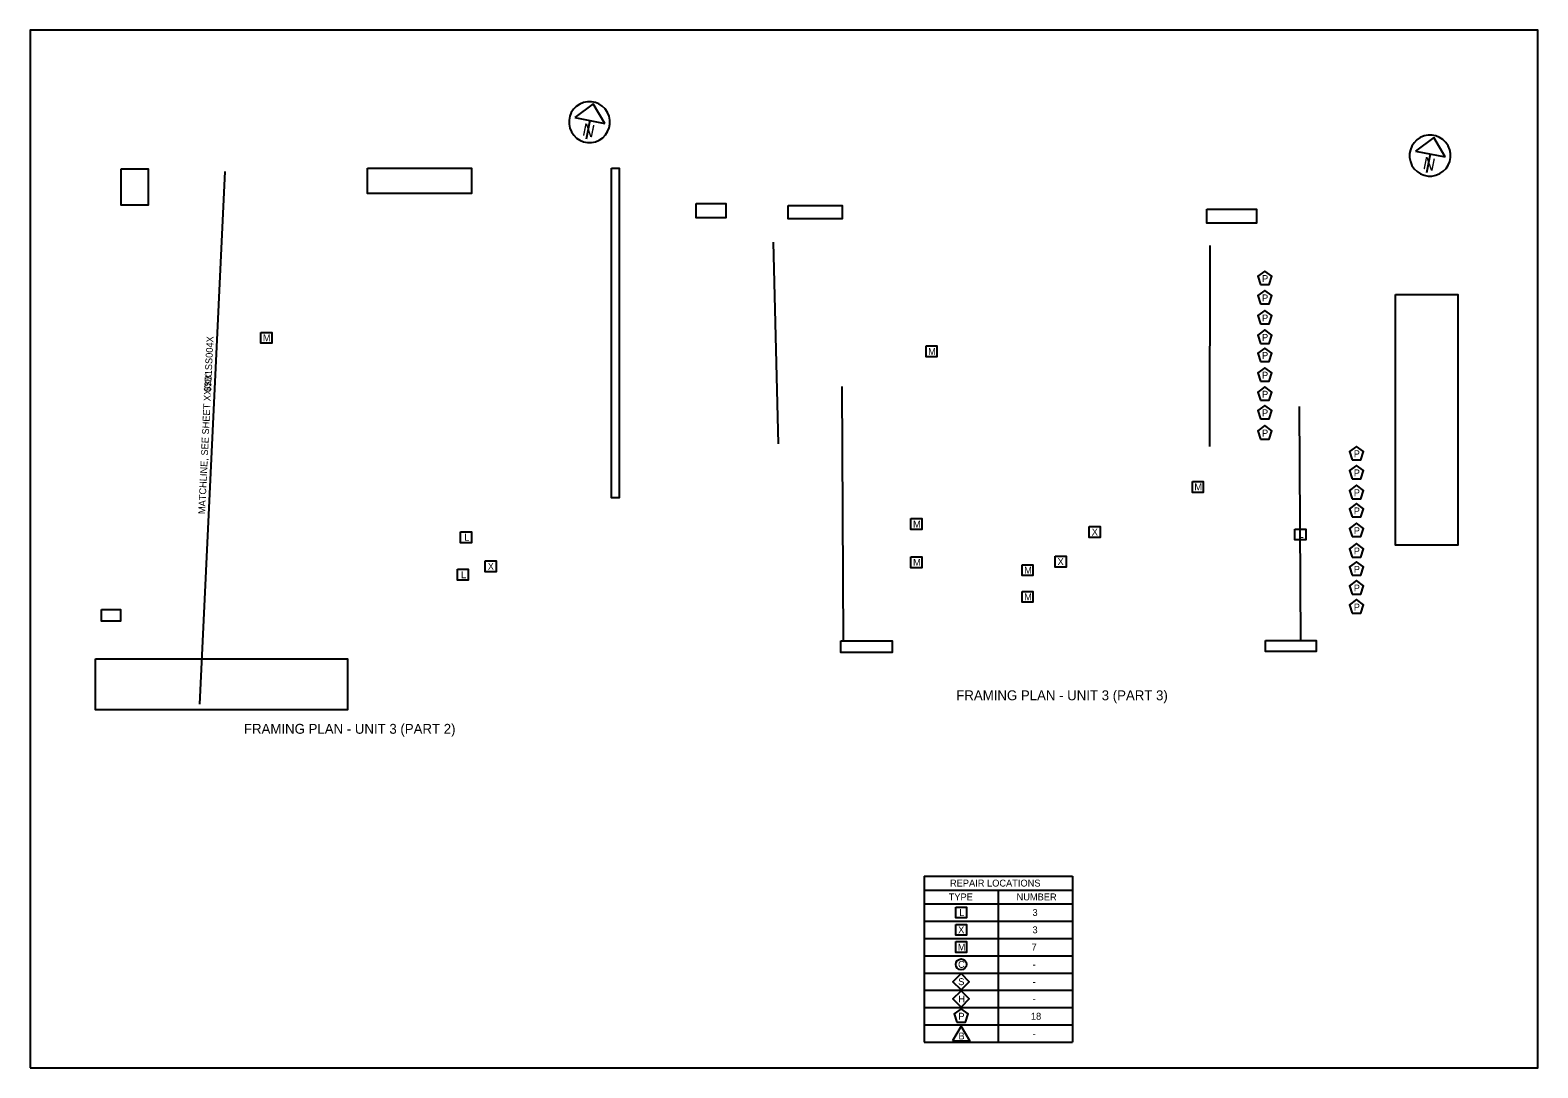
# Model space of a CAD drawing. Extents: x 100 to 130.5, y 100 to 121.
import ezdxf

# ---------------------------------------------------------------- set-up
doc = ezdxf.new("R2010")
doc.units = 0
for name, color, linetype in [('BR_P_Gen_Text', 7, 'Continuous'), ('BR_X_Sub_Centerline', 7, 'Continuous'), ('BR_X_Sub_Text', 7, 'Continuous'), ('SC_Scratch1', 7, 'Continuous'), ('SH_Data', 7, 'Continuous'), ('SH_Masking', 7, 'Continuous')]:
    doc.layers.add(name, color=color, linetype=linetype)

msp = doc.modelspace()

# ---------------------------------------------------------------- linework, layer by layer
at = {"layer": 'BR_P_Gen_Text'}
for p, q in [((103.94, 118.139), (103.427, 107.361)), ((118.083, 103.879), (118.083, 100.519)), ((118.083, 103.879), (121.083, 103.879)), ((121.083, 103.879), (121.083, 100.519)), ((118.083, 103.599), (121.083, 103.599)), ((119.583, 103.599), (119.583, 100.519)), ((118.083, 103.319), (121.083, 103.319)), ((118.083, 102.969), (121.083, 102.969)), ((118.083, 102.619), (121.083, 102.619)), ((118.083, 102.269), (121.083, 102.269)), ((118.083, 101.919), (121.083, 101.919)), ((118.083, 101.569), (121.083, 101.569)), ((118.083, 101.219), (121.083, 101.219)), ((118.083, 100.869), (121.083, 100.869)), ((118.083, 100.519), (121.083, 100.519))]:
    msp.add_line(p, q, dxfattribs=at)
for points in [[(124.888, 115.85), (125.064, 115.85), (125.119, 116.018), (124.976, 116.122), (124.833, 116.018)], [(124.888, 115.459), (125.064, 115.459), (125.119, 115.627), (124.976, 115.731), (124.833, 115.627)], [(124.888, 115.054), (125.064, 115.054), (125.119, 115.222), (124.976, 115.325), (124.833, 115.222)], [(104.666, 114.883), (104.886, 114.883), (104.886, 114.663), (104.666, 114.663)], [(124.888, 114.66), (125.064, 114.66), (125.119, 114.828), (124.976, 114.932), (124.833, 114.828)], [(118.124, 114.609), (118.344, 114.609), (118.344, 114.389), (118.124, 114.389)], [(124.888, 114.296), (125.064, 114.296), (125.119, 114.463), (124.976, 114.567), (124.833, 114.463)], [(124.888, 113.896), (125.064, 113.896), (125.119, 114.064), (124.976, 114.167), (124.833, 114.064)], [(124.888, 113.51), (125.064, 113.51), (125.119, 113.677), (124.976, 113.781), (124.833, 113.677)], [(124.888, 113.133), (125.064, 113.133), (125.119, 113.301), (124.976, 113.405), (124.833, 113.301)], [(124.888, 112.725), (125.064, 112.725), (125.119, 112.892), (124.976, 112.996), (124.833, 112.892)], [(126.744, 112.306), (126.92, 112.306), (126.975, 112.474), (126.832, 112.577), (126.689, 112.474)], [(126.744, 111.919), (126.92, 111.919), (126.975, 112.086), (126.832, 112.19), (126.689, 112.086)], [(123.511, 111.866), (123.731, 111.866), (123.731, 111.646), (123.511, 111.646)], [(126.744, 111.517), (126.92, 111.517), (126.975, 111.685), (126.832, 111.789), (126.689, 111.685)], [(126.744, 111.149), (126.92, 111.149), (126.975, 111.316), (126.832, 111.42), (126.689, 111.316)], [(117.819, 111.114), (118.039, 111.114), (118.039, 110.894), (117.819, 110.894)], [(126.744, 110.75), (126.92, 110.75), (126.975, 110.917), (126.832, 111.021), (126.689, 110.917)], [(108.709, 110.847), (108.929, 110.847), (108.929, 110.627), (108.709, 110.627)], [(121.425, 110.953), (121.645, 110.953), (121.645, 110.733), (121.425, 110.733)], [(125.584, 110.904), (125.804, 110.904), (125.804, 110.684), (125.584, 110.684)], [(126.744, 110.338), (126.92, 110.338), (126.975, 110.506), (126.832, 110.61), (126.689, 110.506)], [(109.208, 110.259), (109.428, 110.259), (109.428, 110.039), (109.208, 110.039)], [(117.819, 110.341), (118.039, 110.341), (118.039, 110.121), (117.819, 110.121)], [(120.067, 110.181), (120.287, 110.181), (120.287, 109.961), (120.067, 109.961)], [(120.735, 110.355), (120.955, 110.355), (120.955, 110.135), (120.735, 110.135)], [(126.744, 109.968), (126.92, 109.968), (126.975, 110.136), (126.832, 110.239), (126.689, 110.136)], [(108.644, 110.089), (108.864, 110.089), (108.864, 109.869), (108.644, 109.869)], [(126.744, 109.589), (126.92, 109.589), (126.975, 109.756), (126.832, 109.86), (126.689, 109.756)], [(120.067, 109.642), (120.287, 109.642), (120.287, 109.422), (120.067, 109.422)], [(126.744, 109.204), (126.92, 109.204), (126.975, 109.371), (126.832, 109.475), (126.689, 109.371)], [(118.723, 103.254), (118.943, 103.254), (118.943, 103.034), (118.723, 103.034)], [(118.723, 102.904), (118.943, 102.904), (118.943, 102.684), (118.723, 102.684)], [(118.723, 102.554), (118.943, 102.554), (118.943, 102.334), (118.723, 102.334)], [(118.833, 101.909), (118.998, 101.744), (118.833, 101.579), (118.668, 101.744)], [(118.833, 101.559), (118.998, 101.394), (118.833, 101.229), (118.668, 101.394)], [(118.745, 100.923), (118.922, 100.923), (118.976, 101.091), (118.833, 101.194), (118.691, 101.091)], [(118.66, 100.544), (119.007, 100.544), (118.833, 100.844)]]:
    msp.add_lwpolyline(points, close=True, dxfattribs=at)
msp.add_circle((118.833, 102.094), 0.11, dxfattribs=at)
at = {"layer": 'BR_X_Sub_Centerline'}
for p, q in [((115.141, 112.626), (115.036, 116.706)), ((123.862, 116.641), (123.861, 112.571)), ((116.451, 108.646), (116.429, 113.791)), ((125.706, 108.631), (125.679, 113.386))]:
    msp.add_line(p, q, dxfattribs=at)
at = {"layer": 'BR_X_Sub_Text'}
for points in [[(115.333, 117.449), (116.43, 117.449), (116.43, 117.184), (115.333, 117.184)], [(123.804, 117.377), (124.806, 117.377), (124.806, 117.096), (123.804, 117.096)], [(116.4, 108.64), (117.435, 108.64), (117.435, 108.407), (116.4, 108.407)], [(124.99, 108.648), (126.016, 108.648), (126.016, 108.424), (124.99, 108.424)]]:
    msp.add_lwpolyline(points, close=True, dxfattribs=at)
at = {"layer": 'SC_Scratch1'}
msp.add_lwpolyline([(100, 100), (130.5, 100), (130.5, 121), (100, 121)], close=True, dxfattribs=at)
at = {"layer": 'SH_Data'}
for p, q in [((111.389, 119.506), (111.02, 119.232)), ((111.623, 119.111), (111.389, 119.506)), ((111.02, 119.232), (111.623, 119.111)), ((111.322, 119.171), (111.245, 118.792)), ((128.393, 118.828), (128.024, 118.554)), ((128.627, 118.433), (128.393, 118.828)), ((128.024, 118.554), (128.627, 118.433)), ((128.325, 118.493), (128.249, 118.114))]:
    msp.add_line(p, q, dxfattribs=at)
for centre in [(111.315, 119.139), (128.319, 118.461)]:
    msp.add_arc(centre, 0.415, 118.4068, 118.3903, dxfattribs=at)
at = {"layer": 'SH_Masking'}
for points in [[(101.842, 118.195), (102.388, 118.195), (102.388, 117.457), (101.842, 117.457)], [(106.822, 118.206), (108.929, 118.206), (108.929, 117.694), (106.822, 117.694)], [(111.758, 118.205), (111.918, 118.205), (111.918, 111.538), (111.758, 111.538)], [(113.473, 117.493), (114.074, 117.493), (114.074, 117.201), (113.473, 117.201)], [(127.618, 115.651), (128.881, 115.651), (128.881, 110.578), (127.618, 110.578)], [(101.445, 109.274), (101.827, 109.274), (101.827, 109.037), (101.445, 109.037)], [(101.325, 108.28), (106.423, 108.28), (106.423, 107.247), (101.325, 107.247)]]:
    msp.add_lwpolyline(points, close=True, dxfattribs=at)

# ---------------------------------------------------------------- texts
at = {"layer": 'BR_P_Gen_Text'}
for s, height, p in [('P', 0.14, (124.92, 115.902)), ('P', 0.14, (124.92, 115.511)), ('P', 0.14, (124.92, 115.105)), ('M', 0.14, (104.708, 114.703)), ('P', 0.14, (124.92, 114.712)), ('M', 0.14, (118.165, 114.429)), ('P', 0.14, (124.92, 114.347)), ('P', 0.14, (124.92, 113.947)), ('P', 0.14, (124.92, 113.561)), ('P', 0.14, (124.92, 113.185)), ('P', 0.14, (124.92, 112.776)), ('P', 0.14, (126.776, 112.357)), ('P', 0.14, (126.776, 111.97)), ('M', 0.14, (123.552, 111.686)), ('P', 0.14, (126.776, 111.569)), ('P', 0.14, (126.776, 111.2)), ('M', 0.14, (117.861, 110.934)), ('L', 0.14, (108.781, 110.667)), ('X', 0.14, (121.475, 110.773)), ('L', 0.14, (125.656, 110.724)), ('P', 0.14, (126.776, 110.801)), ('P', 0.14, (126.776, 110.39)), ('X', 0.14, (109.257, 110.079)), ('M', 0.14, (117.861, 110.161)), ('M', 0.14, (120.109, 110.001)), ('X', 0.14, (120.784, 110.175)), ('P', 0.14, (126.776, 110.019)), ('L', 0.14, (108.716, 109.909)), ('M', 0.14, (120.109, 109.462)), ('P', 0.14, (126.776, 109.64)), ('P', 0.14, (126.776, 109.255)), ('FRAMING PLAN - UNIT 3 (PART 3)', 0.2, (118.735, 107.439)), ('FRAMING PLAN - UNIT 3 (PART 2)', 0.2, (104.325, 106.761)), ('REPAIR LOCATIONS', 0.14, (118.608, 103.669)), ('TYPE', 0.14, (118.582, 103.389)), ('NUMBER', 0.14, (119.955, 103.389)), ('L', 0.14, (118.795, 103.074)), ('3', 0.14, (120.277, 103.074)), ('X', 0.14, (118.773, 102.724)), ('3', 0.14, (120.277, 102.724)), ('M', 0.14, (118.765, 102.374)), ('7', 0.14, (120.258, 102.374)), ('C', 0.14, (118.771, 102.024)), ('-', 0.14, (120.28, 102.024)), ('S', 0.14, (118.775, 101.674)), ('-', 0.14, (120.28, 101.674)), ('H', 0.14, (118.777, 101.324)), ('-', 0.14, (120.28, 101.324)), ('P', 0.14, (118.777, 100.974)), ('18', 0.14, (120.245, 100.974)), ('B', 0.14, (118.779, 100.574)), ('-', 0.14, (120.28, 100.624))]:
    msp.add_text(s, height=height, dxfattribs=at).set_placement(p)
for s, p in [('$$B1SS004X', (103.657, 113.679)), ('MATCHLINE, SEE SHEET XX/XX', (103.539, 111.203))]:
    msp.add_text(s, height=0.14, rotation=87.2737, dxfattribs=at).set_placement(p)
at = {"layer": 'SH_Data'}
for p in [(111.156, 118.874), (128.16, 118.196)]:
    msp.add_text('N', height=0.25, rotation=348.6269, dxfattribs=at).set_placement(p)

doc.saveas('drawing.dxf')
